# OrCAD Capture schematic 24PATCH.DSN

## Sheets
1 24Patch: size A4; title: 24Patch; rev: 1.2; note: 24Patch
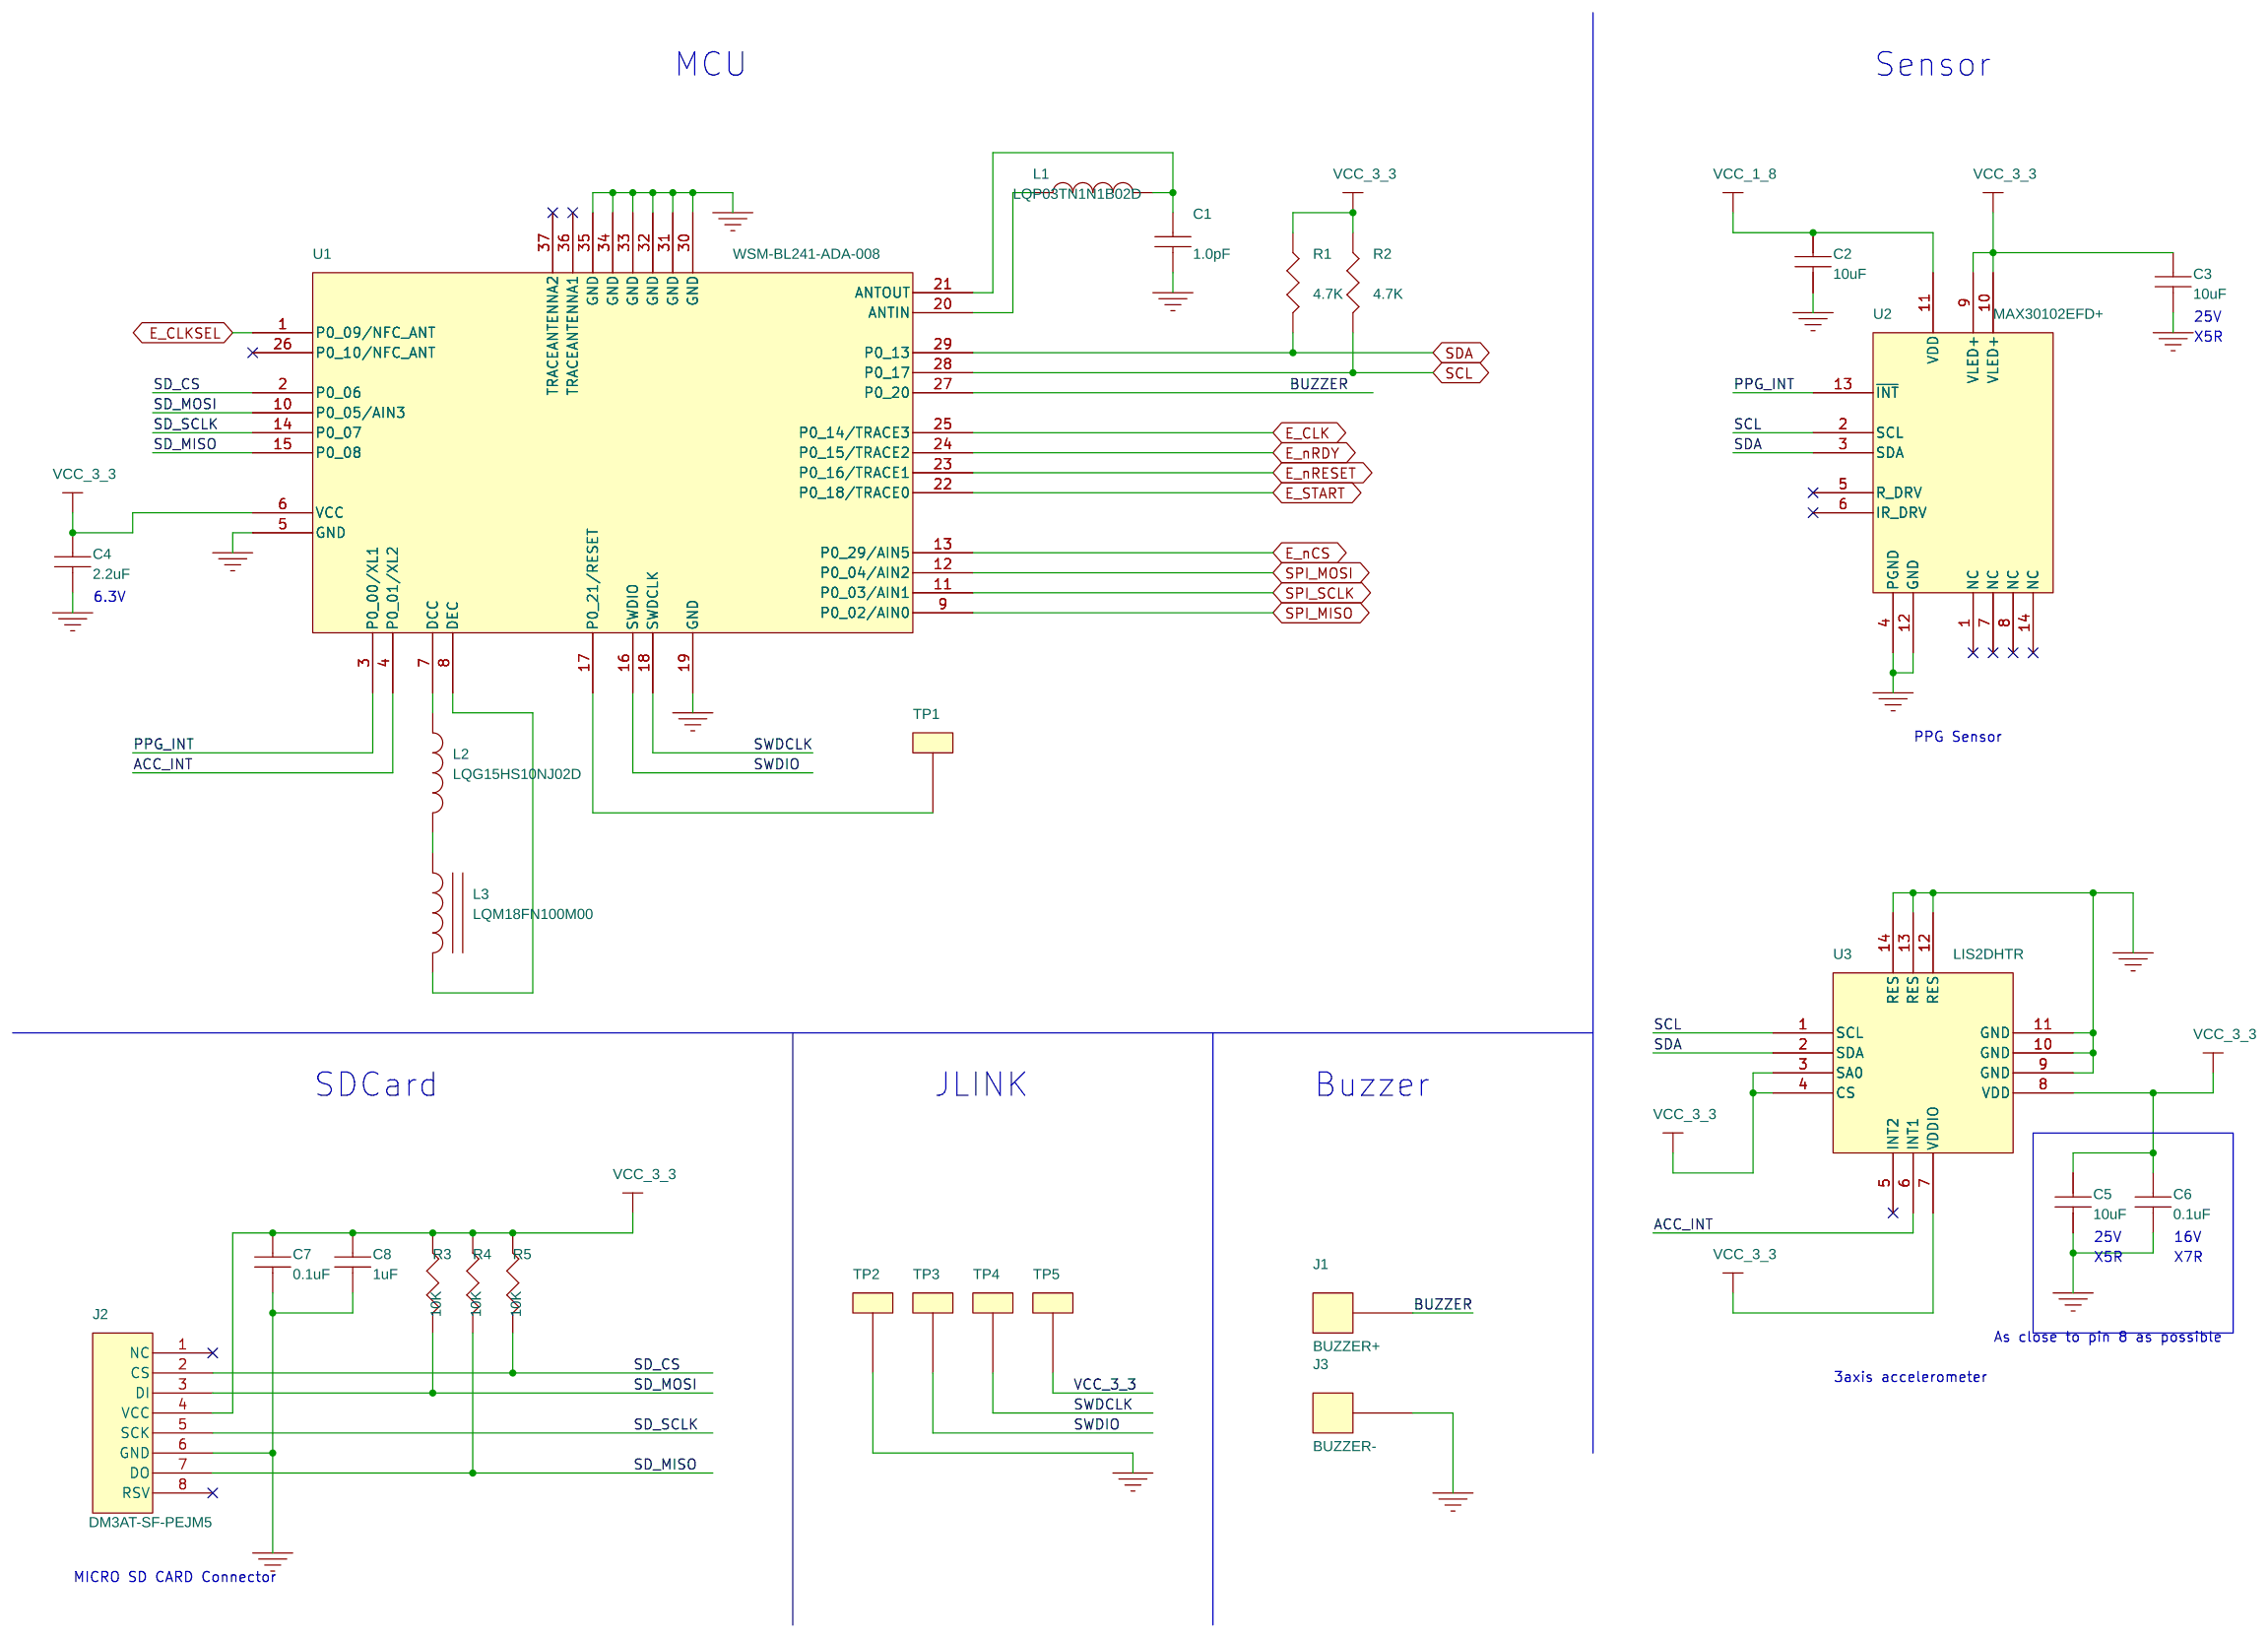
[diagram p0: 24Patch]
2 24Patch_ECG: size A4; title: 24Patch_ECG
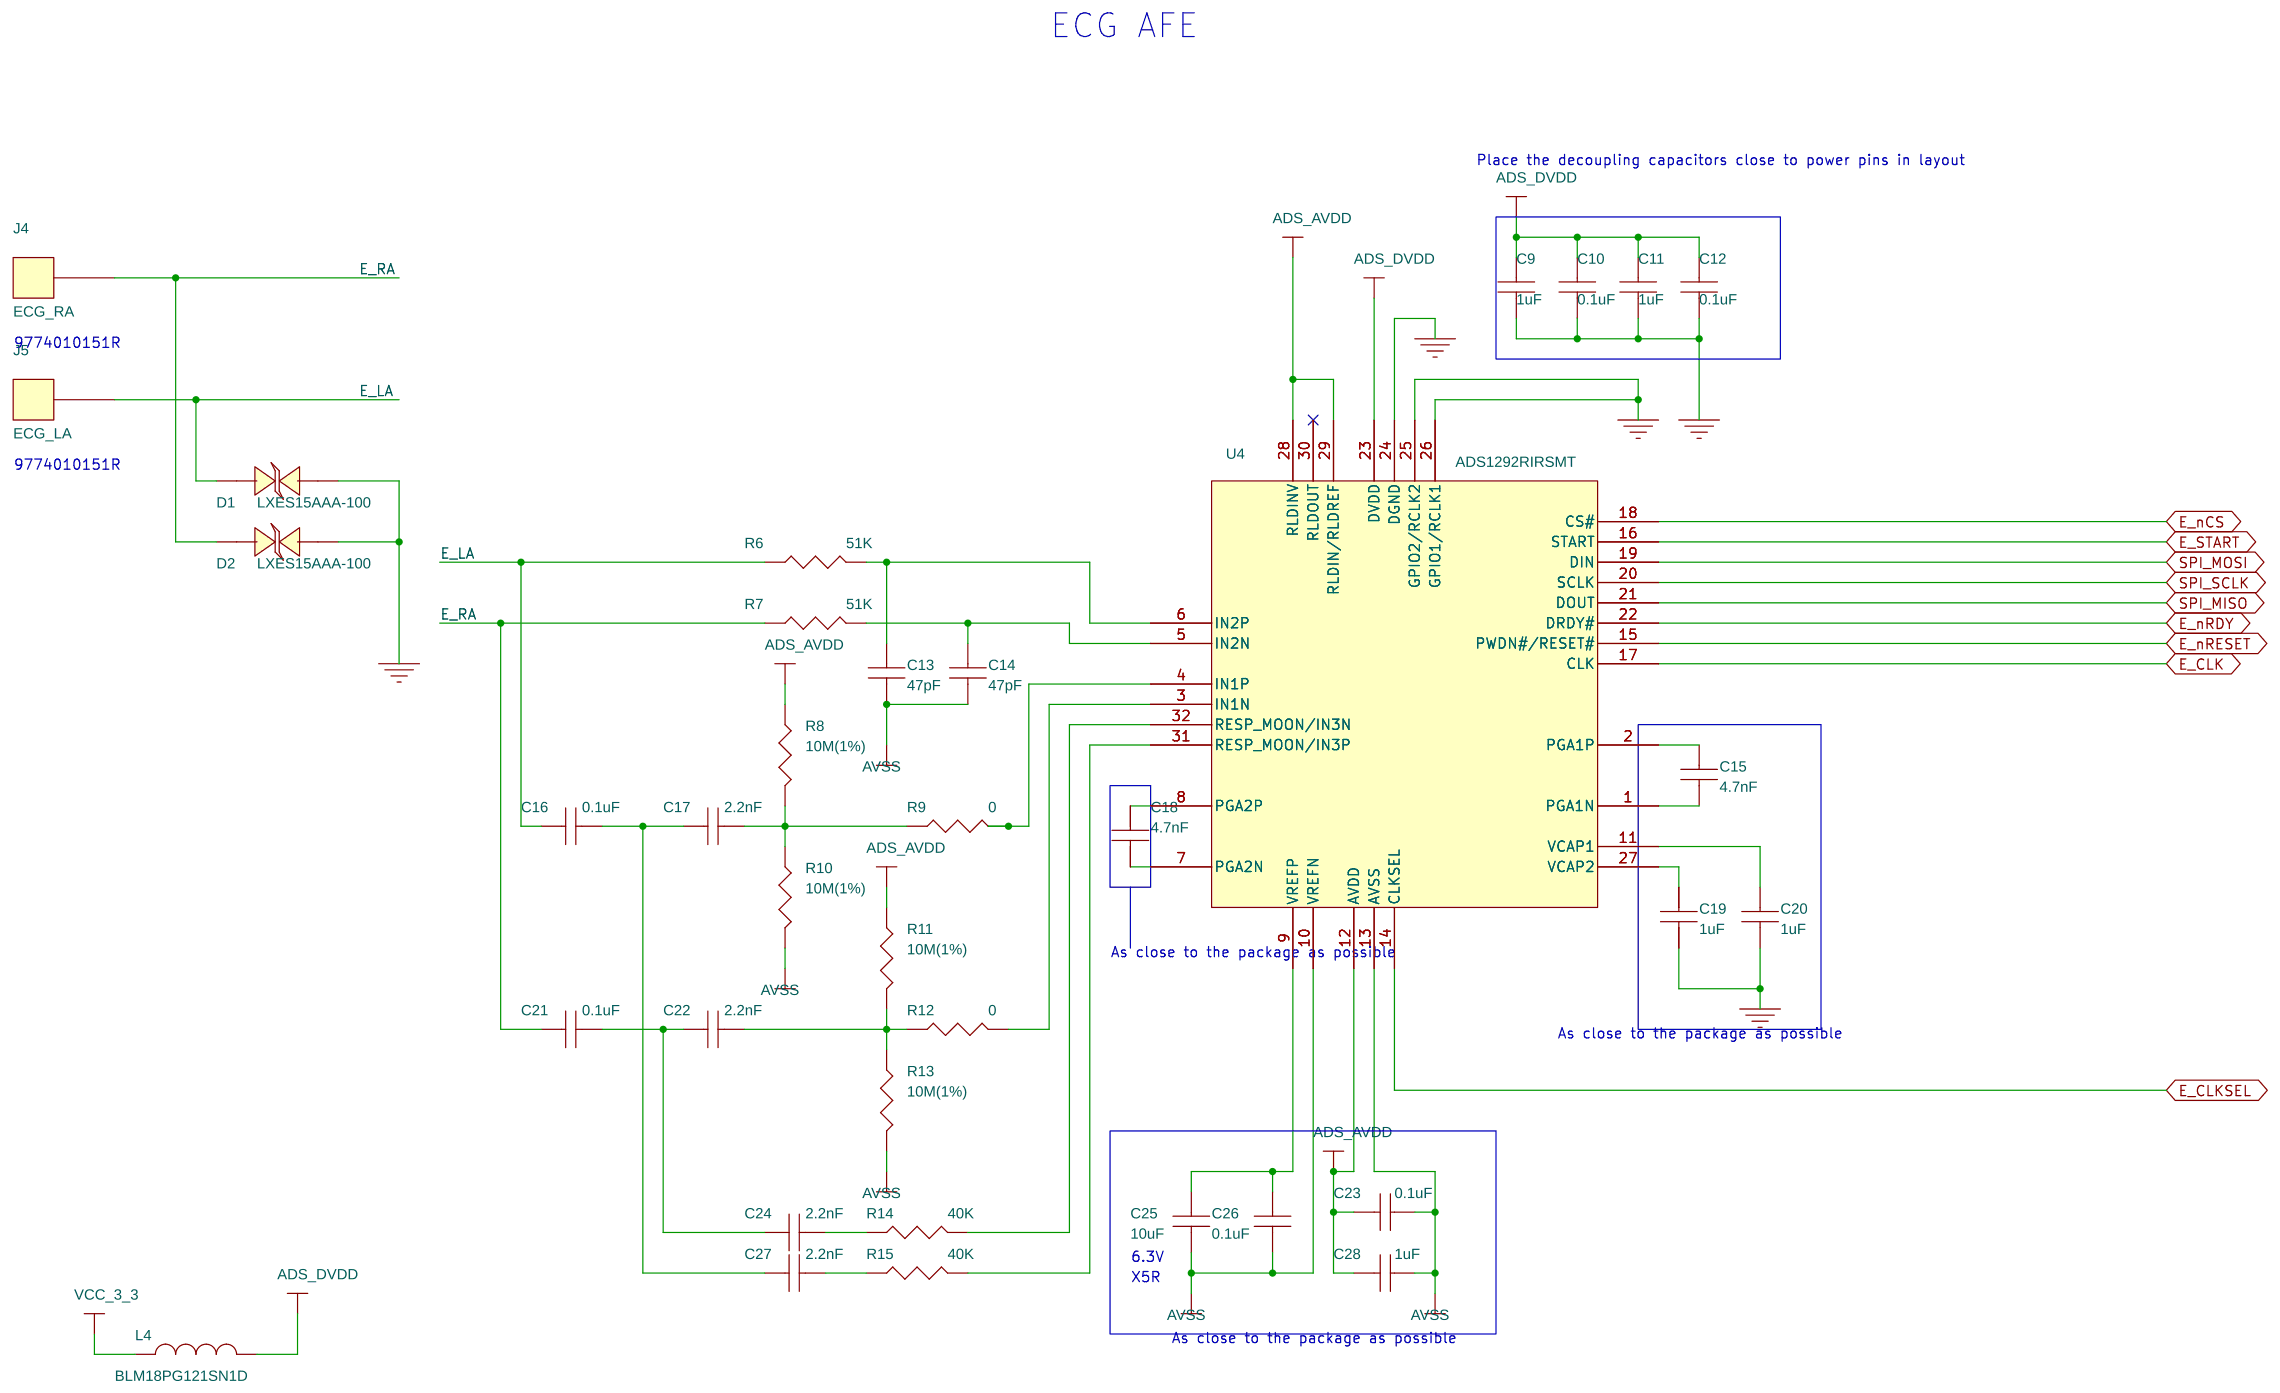
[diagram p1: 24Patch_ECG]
3 24Patch_Power: size A4; title: 24Patch Power Supply
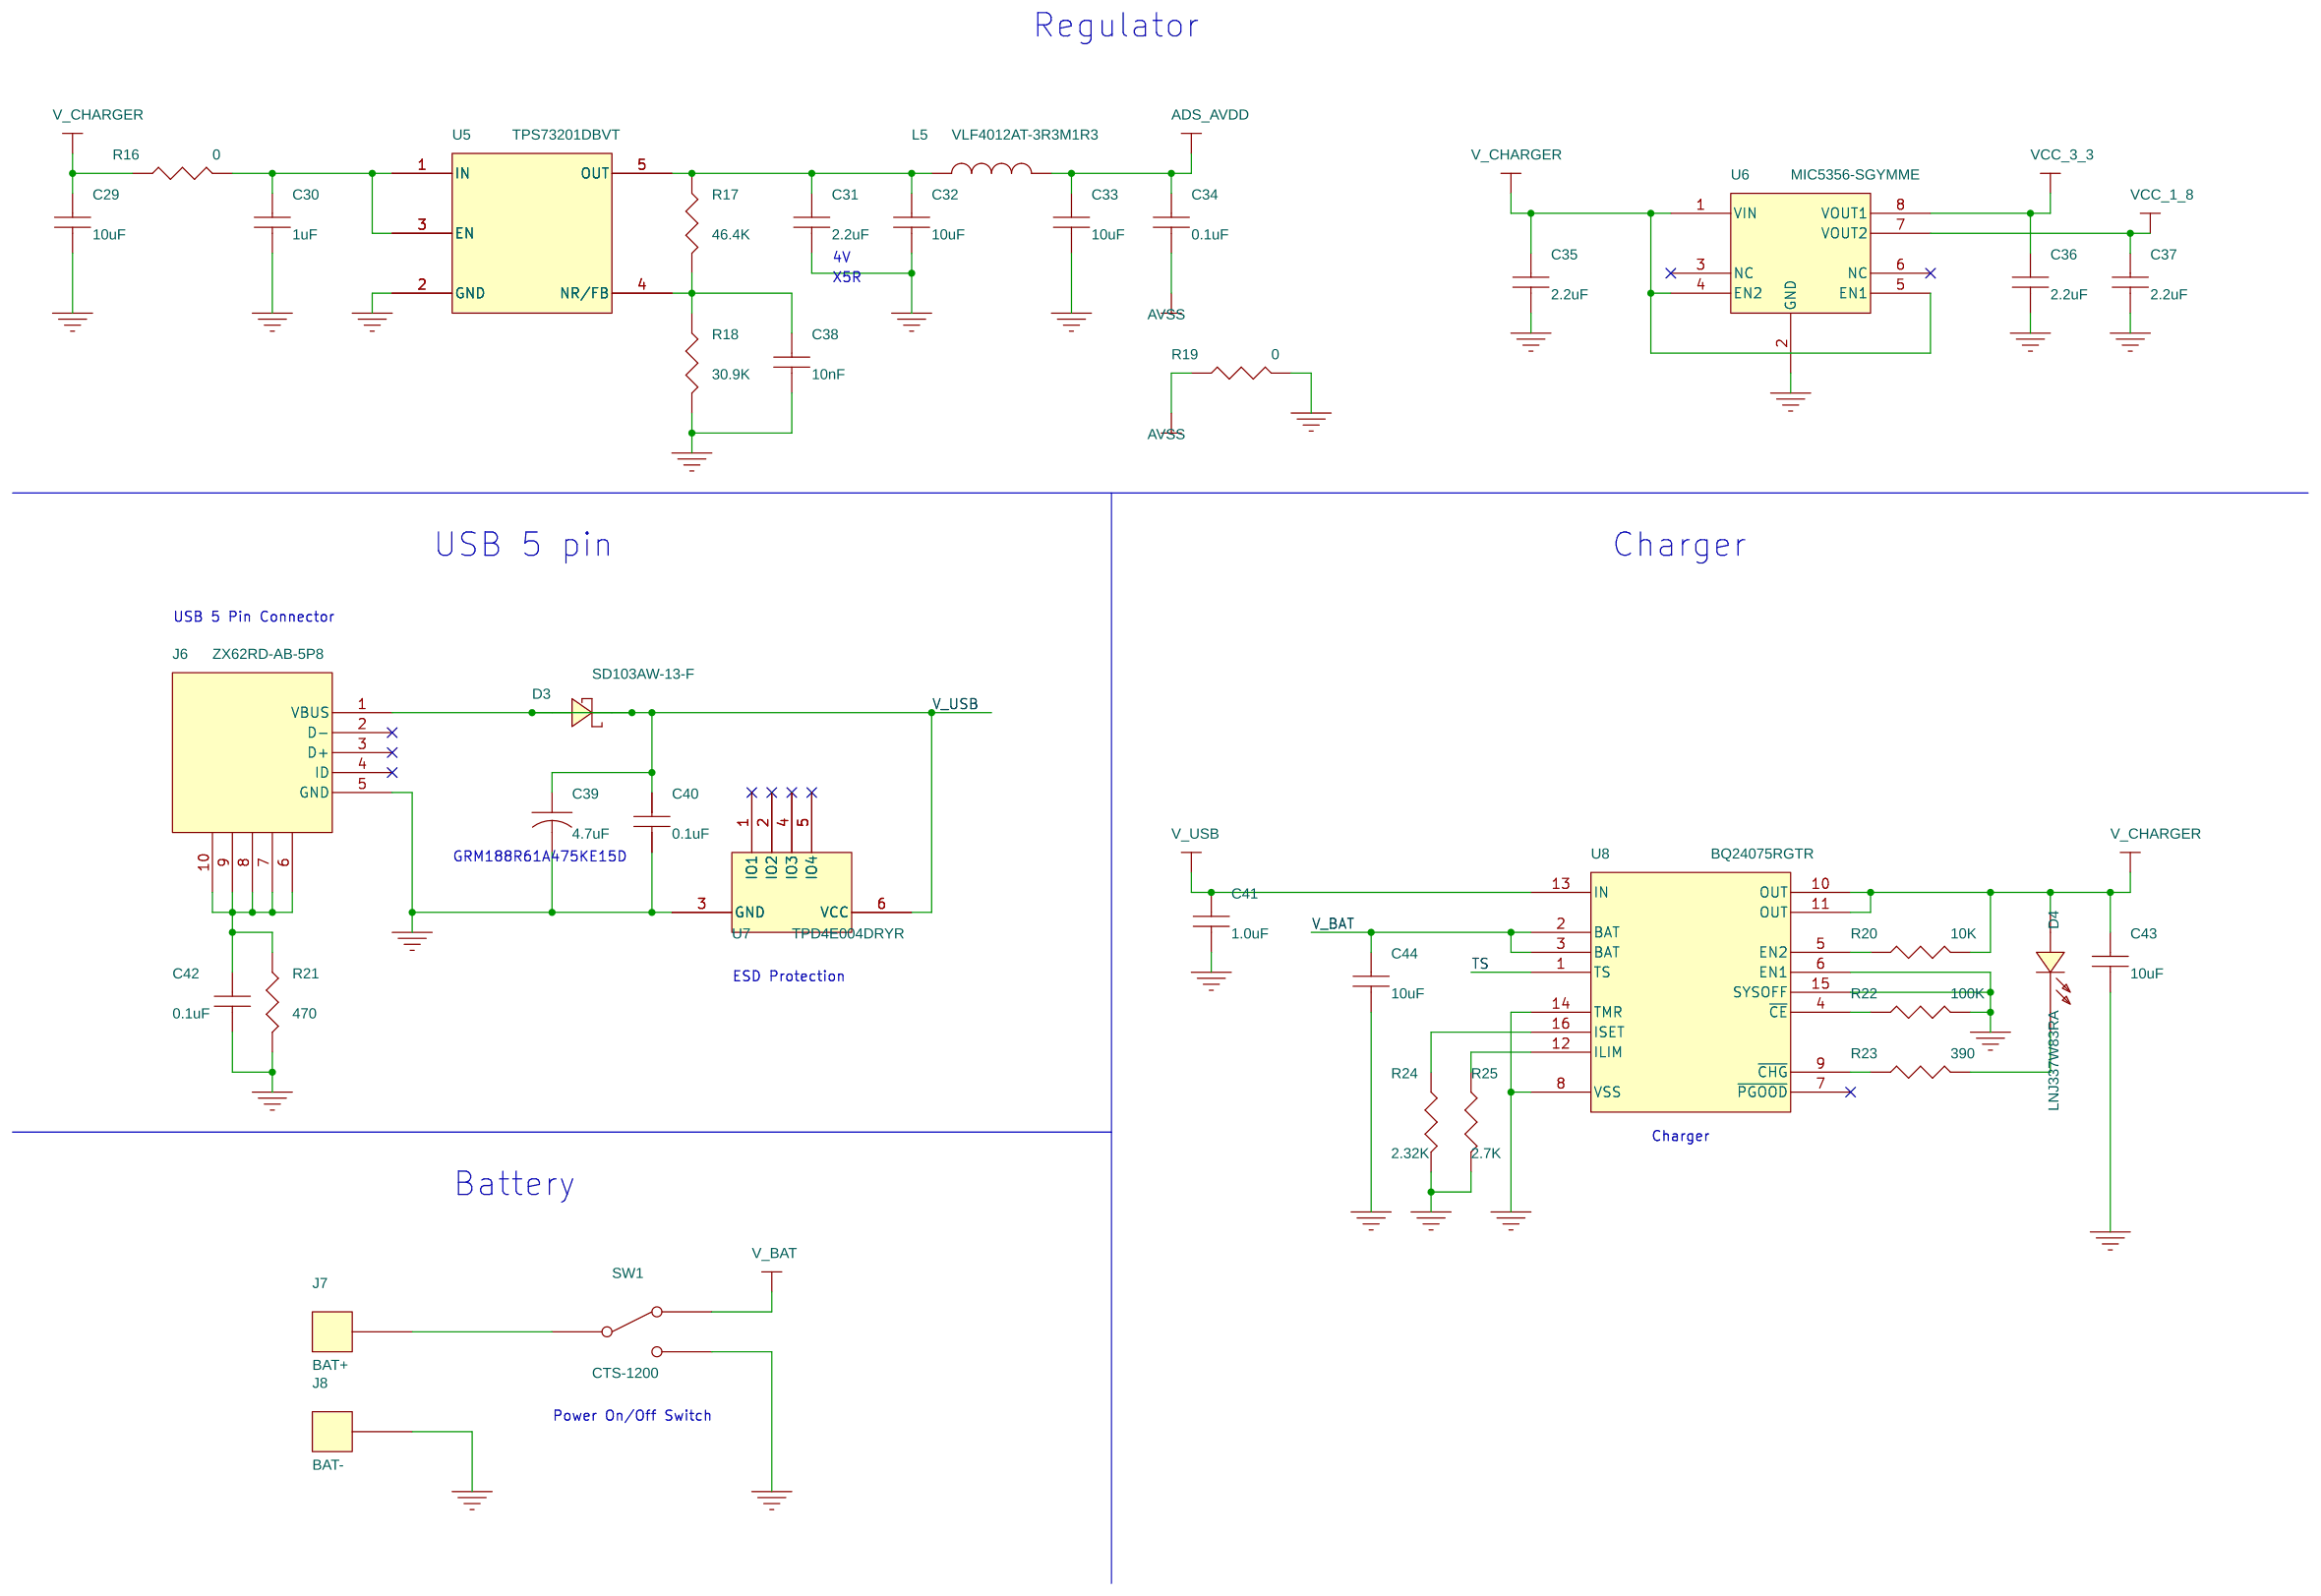
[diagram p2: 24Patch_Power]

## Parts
sheet 24Patch
C1  1.0pF
C2  10uF
C3  10uF
C4  2.2uF
C5  10uF
C6  0.1uF
C7  0.1uF
C8  1uF
J1  BUZZER+
J2  DM3AT-SF-PEJM5
J3  BUZZER-
L1  LQP03TN1N1B02D
L2  LQG15HS10NJ02D
L3  LQM18FN100M00
R1  4.7K
R2  4.7K
R3  10K
R4  10K
R5  10K
TP1  TEST POINT
TP2  TEST POINT
TP3  TEST POINT
TP4  TEST POINT
TP5  TEST POINT
U1  WSM-BL241-ADA-008
U2  MAX30102EFD+
U3  LIS2DHTR
sheet 24Patch_ECG
C9  1uF
C10  0.1uF
C11  1uF
C12  0.1uF
C13  47pF
C14  47pF
C15  4.7nF
C16  0.1uF
C17  2.2nF
C18  4.7nF
C19  1uF
C20  1uF
C21  0.1uF
C22  2.2nF
C23  0.1uF
C24  2.2nF
C25  10uF
C26  0.1uF
C27  2.2nF
C28  1uF
D1  LXES15AAA-100
D2  LXES15AAA-100
J4  ECG_RA
J5  ECG_LA
L4  BLM18PG121SN1D
R6  51K
R7  51K
R8  10M(1%)
R9  0
R10  10M(1%)
R11  10M(1%)
R12  0
R13  10M(1%)
R14  40K
R15  40K
U4  ADS1292RIRSMT
sheet 24Patch_Power
C29  10uF
C30  1uF
C31  2.2uF
C32  10uF
C33  10uF
C34  0.1uF
C35  2.2uF
C36  2.2uF
C37  2.2uF
C38  10nF
C39  4.7uF
C40  0.1uF
C41  1.0uF
C42  0.1uF
C43  10uF
C44  10uF
D3  SD103AW-13-F
D4  LNJ337W83RA
J6  ZX62RD-AB-5P8
J7  BAT+
J8  BAT-
L5  VLF4012AT-3R3M1R3
R16  0
R17  46.4K
R18  30.9K
R19  0
R20  10K
R21  470
R22  100K
R23  390
R24  2.32K
R25  2.7K
SW1  CTS-1200
U5  TPS73201DBVT
U6  MIC5356-SGYMME
U7  TPD4E004DRYR
U8  BQ24075RGTR

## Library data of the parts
C1-C38 C40-C44 = CAP_NP
J1 J3-J5 J7 J8 = CON1
J2 = DM3AT-SF-PEJM5
L1 L2 L4 L5 = INDUCTOR
L3 = INDUCTOR_IRON
R1-R25 = R
TP1-TP5 = TEST_POINT
U1 = WSM-BL241-ADA-008
U2 = MAX30102EFD+
U3 = LIS2DHTR
D1 D2 = DIODE_TVS_BI-DIR
U4 = ADS1292RIRSMT
C39 = CAP
D3 = DIODE_SCHOTTKY
D4 = LED
J6 = ZX62RD-AB-5P8
SW1 = SW_KEY-SPDT
U5 = TPS73201
U6 = MIC5356-SGYMME
U7 = TPD4E004DRYR
U8 = BQ24075

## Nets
AVSS: C13.2 C14.2 C23.1 C25.2 C26.2 C28.1 C34.2 R10.2 R13.2 R19.1 U4.10(VREFN) U4.13(AVSS)
GND: C1.2 C2.2 C3.2 C4.2 C5.2 C6.2 C7.2 C8.2 C9.2 C10.2 C11.2 C12.2 C19.2 C20.2 C29.2 C30.2 C31.2 C32.2 C33.2 C35.2 C36.2 C37.2 C38.2 C39.2 C40.2 C41.2 C42.2 C43.2 C44.2 D1.2 D2.2 J2.6(GND) J3.1 J6.5(GND) J8.1 R18.2 R19.2 R21.2 R22.2 R24.2 R25.2 SW1.3(NO) TP2.1 U1.5(GND) U1.19(GND) U1.30(GND) U1.31(GND) U1.32(GND) U1.33(GND) U1.34(GND) U1.35(GND) U2.4(PGND) U2.12(GND) U3.9(GND) U3.10(GND) U3.11(GND) U3.12(RES) U3.13(RES) U3.14(RES) U4.24(DGND) U4.25(GPIO2/RCLK2) U4.26(GPIO1/RCLK1) U5.2(GND) U6.2(GND) U7.3(GND) U8.6(EN1) U8.8(VSS) U8.14(TMR) U8.15(SYSOFF)
VCC_1_8: C2.1 C37.1 U2.11(VDD) U6.7(VOUT2)
VCC_3_3: C3.1 C4.1 C5.1 C6.1 C7.1 C8.1 C36.1 J2.4(VCC) L4.1 R1.1 R2.1 R3.1 R4.1 R5.1 TP5.1 U1.6(VCC) U2.9(VLED+) U2.10(VLED+) U3.3(SA0) U3.4(CS) U3.7(VDDIO) U3.8(VDD) U6.8(VOUT1)
ACC_INT: U1.4(P0_01/XL2) U3.6(INT1)
ADS_AVDD: C23.2 C28.2 C33.1 C34.1 L5.2 R8.1 R11.1 U4.12(AVDD) U4.28(RLDINV) U4.29(RLDIN/RLDREF)
ADS_DVDD: C9.1 C10.1 C11.1 C12.1 L4.2 U4.23(DVDD)
BUZZER: J1.1 U1.27(P0_20)
E_CLK: U1.25(P0_14/TRACE3) U4.17(CLK)
E_CLKSEL: U1.1(P0_09/NFC_ANT) U4.14(CLKSEL)
E_LA: C16.1 D1.1 J5.1 R6.1
E_nCS: U1.13(P0_29/AIN5) U4.18(CS#)
E_nRDY: U1.24(P0_15/TRACE2) U4.22(DRDY#)
E_nRESET: U1.23(P0_16/TRACE1) U4.15(PWDN#/RESET#)
E_RA: C21.1 D2.1 J4.1 R7.1
E_START: U1.22(P0_18/TRACE0) U4.16(START)
PPG_INT: U1.3(P0_00/XL1) U2.13(~{INT})
SCL: R2.2 U1.28(P0_17) U2.2(SCL) U3.1(SCL)
SD_CS: J2.2(CS) R5.2 U1.2(P0_06)
SD_MISO: J2.7(DO) R4.2 U1.15(P0_08)
SD_MOSI: J2.3(DI) R3.2 U1.10(P0_05/AIN3)
SD_SCLK: J2.5(SCK) U1.14(P0_07)
SDA: R1.2 U1.29(P0_13) U2.3(SDA) U3.2(SDA)
SPI_MISO: U1.9(P0_02/AIN0) U4.21(DOUT)
SPI_MOSI: U1.12(P0_04/AIN2) U4.19(DIN)
SPI_SCLK: U1.11(P0_03/AIN1) U4.20(SCLK)
SWDCLK: TP4.1 U1.18(SWDCLK)
SWDIO: TP3.1 U1.16(SWDIO)
TS: U8.1(TS)
V_BAT: C44.1 SW1.8(NC) U8.2(BAT) U8.3(BAT)
V_CHARGER: C29.1 C35.1 C43.1 D4.2(ANODE) R16.1 R20.2 U6.1(VIN) U6.4(EN2) U6.5(EN1) U8.10(OUT) U8.11(OUT)
V_USB: C39.1 C40.1 C41.1 D3.1(ANODE) D3.2(CATHODE) J6.1(VBUS) U7.6(VCC) U8.13(IN)
N00732: C31.1 C32.1 L5.1 R17.1 U5.5(OUT)
N00736: C38.1 R17.2 R18.1 U5.4(NR/FB)
N01050: C30.1 R16.2 U5.1(IN) U5.3(EN)
N02515: C42.1 J6.6 J6.7 J6.8 J6.9 J6.10 R21.1
N13916: C13.1 R6.2 U4.6(IN2P)
N14004: C14.1 R7.2 U4.5(IN2N)
N14266: R9.2 U4.4(IN1P)
N14441: C17.2 R8.2 R9.1 R10.1
N14716: C16.2 C17.1 C27.1
N14796: R12.2 U4.3(IN1N)
N14963: C22.2 R11.2 R12.1 R13.1
N15164: C21.2 C22.1 C24.1
N15196: R14.2 U4.32(RESP_MOON/IN3N)
N15211: R15.2 U4.31(RESP_MOON/IN3P)
N15507: C24.2 R14.1
N15511: C27.2 R15.1
N15587: C18.1 U4.8(PGA2P)
N15591: C18.2 U4.7(PGA2N)
N15672: C25.1 C26.1 U4.9(VREFP)
N16643: C19.1 U4.27(VCAP2)
N16652: C20.1 U4.11(VCAP1)
N16814: C15.1 U4.2(PGA1P)
N16818: C15.2 U4.1(PGA1N)
N25121: L2.2 L3.1
N25125: L2.1 U1.7(DCC)
N25129: L3.2 U1.8(DEC)
N31091: L1.1 U1.20(ANTIN)
N31106: C1.1 L1.2 U1.21(ANTOUT)
N32045: TP1.1 U1.17(P0_21/RESET)
N38879: R24.1 U8.16(ISET)
N38888: R25.1 U8.12(ILIM)
N39340: R20.1 U8.5(EN2)
N39557: R22.1 U8.4(~{CE})
N41222: D4.1(CATHODE) R23.2
N41343: R23.1 U8.9(~{CHG})
N43660: J7.1 SW1.1(COMMON)

Not connected (* = marked no-connect by the designer): J2 1(NC)* 8(RSV)*; J6 2(D-)* 3(D+)* 4(ID)*; U1 26(P0_10/NFC_ANT)* 36(TRACEANTENNA1)* 37(TRACEANTENNA2)*; U2 1(NC)* 5(R_DRV)* 6(IR_DRV)* 7(NC)* 8(NC)* 14(NC)*; U3 5(INT2)*; U4 30(RLDOUT)*; U6 3(NC)* 6(NC)*; U7 1(IO1)* 2(IO2)* 4(IO3)* 5(IO4)*; U8 7(~{PGOOD})*

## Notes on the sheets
sheet 1
- MCU
- Sensor
- 25V
- X5R
- 6.3V
- PPG Sensor
- SDCard
- JLINK
- Buzzer
- 25V
- 16V
- X5R
- X7R
- As close to pin 8 as possible
- 3axis accelerometer
- MICRO SD CARD Connector
sheet 2
- ECG AFE
- Place the decoupling capacitors close to power pins in layout
- 9774010151R
- 9774010151R
- As close to the package as possible
- As close to the package as possible
- 6.3V
- X5R
- As close to the package as possible
sheet 3
- Regulator
- 4V
- X5R
- USB 5 pin
- Charger
- USB 5 Pin Connector
- GRM188R61A475KE15D
- ESD Protection
- Charger
- Battery
- Power On/Off Switch
